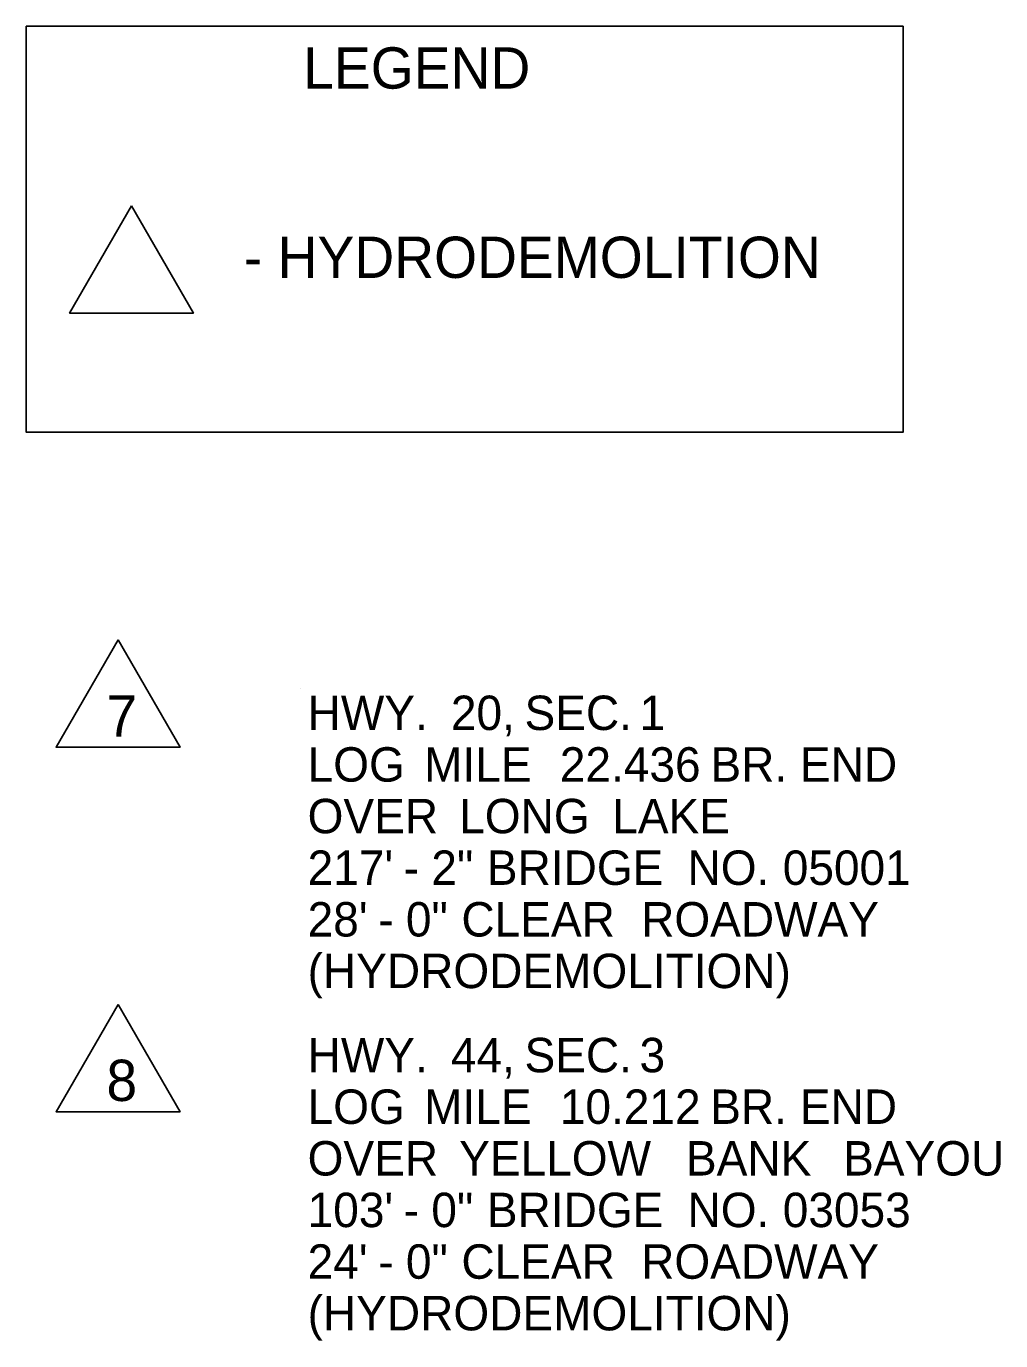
# Model space of a CAD drawing. Extents: x -33639 to 34530, y -17264 to 5867.
# Drawn here: x 1446 to 3569, y -14271 to -11406 of the extents above; entities that cross this region are included whole.
import ezdxf

# ---------------------------------------------------------------- set-up
doc = ezdxf.new("R2010")
doc.units = 0
for name, color, linetype in [('Default', 7, 'Continuous'), ('R_Annotation', 7, 'Continuous'), ('S_MISC_BOUNDARY', 7, 'Continuous')]:
    doc.layers.add(name, color=color, linetype=linetype)

msp = doc.modelspace()

# ---------------------------------------------------------------- linework, layer by layer
at = {"layer": 'R_Annotation'}
for points in [[(1446, -11406.2), (3356.6, -11406.2), (3356.6, -12290.9), (1446, -12290.9)], [(1675.3, -11797.5), (1810.3, -12031.3), (1540.3, -12031.3)], [(1646, -12743.7), (1781, -12977.5), (1511, -12977.5)], [(1646, -13538.1), (1781, -13771.9), (1511, -13771.9)]]:
    msp.add_lwpolyline(points, close=True, dxfattribs=at)
at = {"layer": 'S_MISC_BOUNDARY'}
msp.add_line((2044.3, -12850), (2044.3, -12850), dxfattribs=at)

# ---------------------------------------------------------------- texts
at = {"layer": 'Default'}
for s, p in [('HWY.', (2059, -12940)), (' 20,', (2343.3, -12940)), (' SEC.', (2503.8, -12940)), (' 1', (2754.4, -12940)), ('LOG', (2059, -13052.5)), (' 22.436', (2580.7, -13052.5)), (' MILE', (2284.9, -13052.5)), (' BR.', (2908.9, -13052.5)), (' END', (3104.1, -13052.5)), ('OVER', (2059, -13165)), (' LONG', (2361.4, -13165)), (' LAKE', (2695, -13165)), ("217'", (2059, -13277.5)), (' 2"', (2300.7, -13277.5)), (' BRIDGE', (2421.7, -13277.5)), (' NO.', (2859, -13277.5)), (' 05001', (3066.5, -13277.5)), (' -', (2240.5, -13277.5)), ("28'", (2059, -13390)), (' 0"', (2245.3, -13390)), (' CLEAR', (2366.3, -13390)), (' ROADWAY', (2757.9, -13390)), (' -', (2185.1, -13390)), ('(HYDRODEMOLITION)', (2059, -13502.5)), ('HWY.', (2059, -13685.9)), (' 44,', (2343.3, -13685.9)), (' SEC.', (2503.8, -13685.9)), (' 3', (2754.4, -13685.9)), ('LOG', (2059, -13798.4)), (' MILE', (2284.9, -13798.4)), (' 10.212', (2580.7, -13798.4)), (' BR.', (2908.5, -13798.4)), (' END', (3103.8, -13798.4)), ('OVER', (2059, -13910.9)), (' YELLOW', (2361.4, -13910.9)), (' BANK', (2855.6, -13910.9)), (' BAYOU', (3198, -13910.9)), ("103'", (2059, -14023.4)), (' 0"', (2300.7, -14023.4)), (' BRIDGE', (2421.7, -14023.4)), (' NO.', (2859, -14023.4)), (' 03053', (3066.5, -14023.4)), (' -', (2240.5, -14023.4)), ("24'", (2059, -14135.9)), (' 0"', (2245.3, -14135.9)), (' CLEAR', (2366.3, -14135.9)), (' ROADWAY', (2757.9, -14135.9)), (' -', (2185.1, -14135.9)), ('(HYDRODEMOLITION)', (2059, -14248.4))]:
    msp.add_text(s, height=75, dxfattribs=at).set_placement(p)
at = {"layer": 'R_Annotation'}
for s, p in [('LEGEND', (2049.3, -11542.1)), ('- HYDRODEMOLITION', (1920.1, -11954.7)), ('7', (1620.6, -12954.1)), ('8', (1620.6, -13748.5))]:
    msp.add_text(s, height=90, dxfattribs=at).set_placement(p)

doc.saveas('drawing.dxf')
